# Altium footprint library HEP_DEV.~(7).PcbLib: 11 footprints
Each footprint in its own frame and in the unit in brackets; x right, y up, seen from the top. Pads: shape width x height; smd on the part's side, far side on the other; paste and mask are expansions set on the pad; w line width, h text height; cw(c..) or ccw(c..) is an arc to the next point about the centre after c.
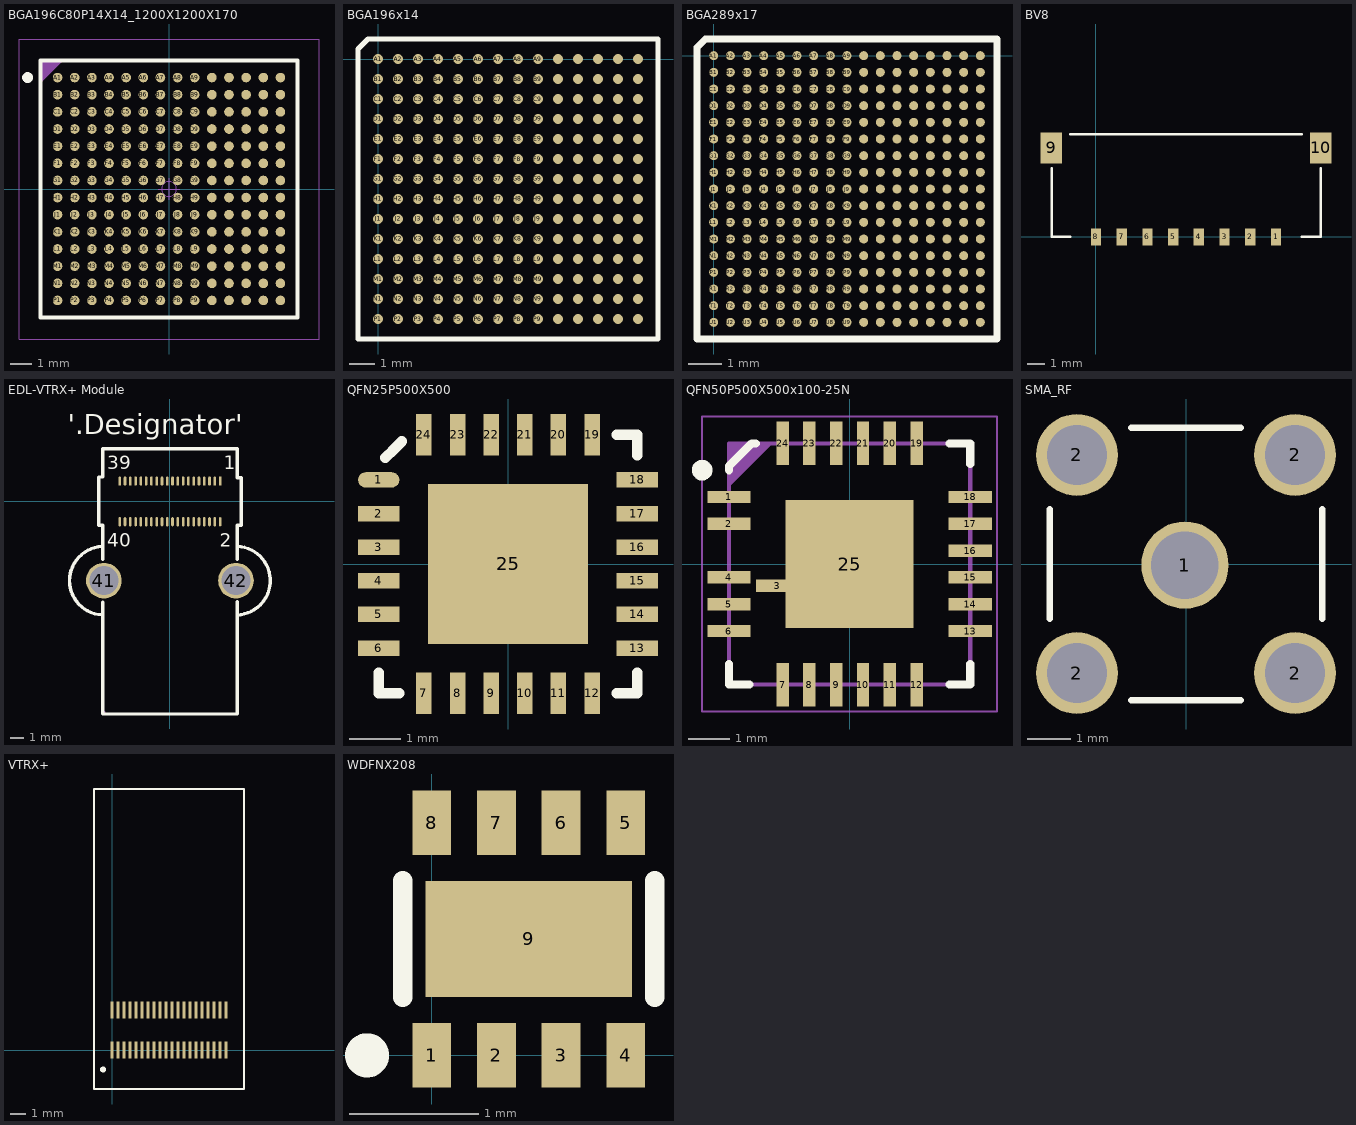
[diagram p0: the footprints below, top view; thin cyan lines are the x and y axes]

## BGA196C80P14X14_1200X1200X170 [mm] "BGA, 0.80mm Pitch, Square; 196 Pin, 14 Columns X 14 Rows, 12.00mm X 12.00mm X 1.70mm H"
height 1.7
pads (196):
  round 0.45 smd: A1(-5.2,5.2) A2(-4.4,5.2) A3(-3.6,5.2) A4(-2.8,5.2) A5(-2,5.2) A6(-1.2,5.2) A7(-0.4,5.2) A8(0.4,5.2) A9(1.2,5.2) A10(2,5.2) A11(2.8,5.2) A12(3.6,5.2) A13(4.4,5.2) A14(5.2,5.2) B1(-5.2,4.4) B2(-4.4,4.4) B3(-3.6,4.4) B4(-2.8,4.4) B5(-2,4.4) B6(-1.2,4.4) B7(-0.4,4.4) B8(0.4,4.4) B9(1.2,4.4) B10(2,4.4) B11(2.8,4.4) B12(3.6,4.4) B13(4.4,4.4) B14(5.2,4.4) C1(-5.2,3.6) C2(-4.4,3.6) C3(-3.6,3.6) C4(-2.8,3.6) C5(-2,3.6) C6(-1.2,3.6) C7(-0.4,3.6) C8(0.4,3.6) C9(1.2,3.6) C10(2,3.6) C11(2.8,3.6) C12(3.6,3.6) C13(4.4,3.6) C14(5.2,3.6) D1(-5.2,2.8) D2(-4.4,2.8) D3(-3.6,2.8) D4(-2.8,2.8) D5(-2,2.8) D6(-1.2,2.8) D7(-0.4,2.8) D8(0.4,2.8) D9(1.2,2.8) D10(2,2.8) D11(2.8,2.8) D12(3.6,2.8) D13(4.4,2.8) D14(5.2,2.8) E1(-5.2,2) E2(-4.4,2) E3(-3.6,2) E4(-2.8,2) E5(-2,2) E6(-1.2,2) E7(-0.4,2) E8(0.4,2) E9(1.2,2) E10(2,2) E11(2.8,2) E12(3.6,2) E13(4.4,2) E14(5.2,2) F1(-5.2,1.2) F2(-4.4,1.2) F3(-3.6,1.2) F4(-2.8,1.2) F5(-2,1.2) F6(-1.2,1.2) F7(-0.4,1.2) F8(0.4,1.2) F9(1.2,1.2) F10(2,1.2) F11(2.8,1.2) F12(3.6,1.2) F13(4.4,1.2) F14(5.2,1.2) G1(-5.2,0.4) G2(-4.4,0.4) G3(-3.6,0.4) G4(-2.8,0.4) G5(-2,0.4) G6(-1.2,0.4) G7(-0.4,0.4) G8(0.4,0.4) G9(1.2,0.4) G10(2,0.4) G11(2.8,0.4) G12(3.6,0.4) G13(4.4,0.4) G14(5.2,0.4) H1(-5.2,-0.4) H2(-4.4,-0.4) H3(-3.6,-0.4) H4(-2.8,-0.4) H5(-2,-0.4) H6(-1.2,-0.4) H7(-0.4,-0.4) H8(0.4,-0.4) H9(1.2,-0.4) H10(2,-0.4) H11(2.8,-0.4) H12(3.6,-0.4) H13(4.4,-0.4) H14(5.2,-0.4) J1(-5.2,-1.2) J2(-4.4,-1.2) J3(-3.6,-1.2) J4(-2.8,-1.2) J5(-2,-1.2) J6(-1.2,-1.2) J7(-0.4,-1.2) J8(0.4,-1.2) J9(1.2,-1.2) J10(2,-1.2) J11(2.8,-1.2) J12(3.6,-1.2) J13(4.4,-1.2) J14(5.2,-1.2) K1(-5.2,-2) K2(-4.4,-2) K3(-3.6,-2) K4(-2.8,-2) K5(-2,-2) K6(-1.2,-2) K7(-0.4,-2) K8(0.4,-2) K9(1.2,-2) K10(2,-2) K11(2.8,-2) K12(3.6,-2) K13(4.4,-2) K14(5.2,-2) L1(-5.2,-2.8) L2(-4.4,-2.8) L3(-3.6,-2.8) L4(-2.8,-2.8) L5(-2,-2.8) L6(-1.2,-2.8) L7(-0.4,-2.8) L8(0.4,-2.8) L9(1.2,-2.8) L10(2,-2.8) L11(2.8,-2.8) L12(3.6,-2.8) L13(4.4,-2.8) L14(5.2,-2.8) M1(-5.2,-3.6) M2(-4.4,-3.6) M3(-3.6,-3.6) M4(-2.8,-3.6) M5(-2,-3.6) M6(-1.2,-3.6) M7(-0.4,-3.6) M8(0.4,-3.6) M9(1.2,-3.6) M10(2,-3.6) M11(2.8,-3.6) M12(3.6,-3.6) M13(4.4,-3.6) M14(5.2,-3.6) N1(-5.2,-4.4) N2(-4.4,-4.4) N3(-3.6,-4.4) N4(-2.8,-4.4) N5(-2,-4.4) N6(-1.2,-4.4) N7(-0.4,-4.4) N8(0.4,-4.4) N9(1.2,-4.4) N10(2,-4.4) N11(2.8,-4.4) N12(3.6,-4.4) N13(4.4,-4.4) N14(5.2,-4.4) P1(-5.2,-5.2) P2(-4.4,-5.2) P3(-3.6,-5.2) P4(-2.8,-5.2) P5(-2,-5.2) P6(-1.2,-5.2) P7(-0.4,-5.2) P8(0.4,-5.2) P9(1.2,-5.2) P10(2,-5.2) P11(2.8,-5.2) P12(3.6,-5.2) P13(4.4,-5.2) P14(5.2,-5.2)
Top Overlay:
  circle w0.25: c-6.6,5.2 r0.125
  lines w0.2: -6,-6 -6,6 6,6 6,-6 -6,-6
Mechanical 14:
  lines w0.1: -6,5 -5,6 ; -6,5.1 -5.1,6 ; -6,5.2 -5.2,6 ; -6,5.3 -5.3,6 ; -6,5.4 -5.4,6 ; -6,5.5 -5.5,6 ; -6,5.6 -5.6,6 ; -6,5.7 -5.7,6 ; -6,5.8 -5.8,6 ; -6,5.9 -5.9,6 ; -6,-6 -6,6 6,6 6,-6 -6,-6
Mechanical 15:
  circle w0.05: c0,0 r0.35
  lines w0.05: -0.5,0 0.5,0 ; 0,-0.5 0,0.5 ; -7,-7 -7,7 7,7 7,-7 -7,-7
3D body "BGA196C80P14X14_1200X1200X170.stp": height 1.7, standoff 0, extent -6,-6 6,6

## BGA196x14 [mm]
pads (196):
  round 0.4 smd: A1(0,0) A2(0.8,0) A3(1.6,0) A4(2.4,0) A5(3.2,0) A6(4,0) A7(4.8,0) A8(5.6,0) A9(6.4,0) A10(7.2,0) A11(8,0) A12(8.8,0) A13(9.6,0) A14(10.4,0) B1(0,-0.8) B2(0.8,-0.8) B3(1.6,-0.8) B4(2.4,-0.8) B5(3.2,-0.8) B6(4,-0.8) B7(4.8,-0.8) B8(5.6,-0.8) B9(6.4,-0.8) B10(7.2,-0.8) B11(8,-0.8) B12(8.8,-0.8) B13(9.6,-0.8) B14(10.4,-0.8) C1(0,-1.6) C2(0.8,-1.6) C3(1.6,-1.6) C4(2.4,-1.6) C5(3.2,-1.6) C6(4,-1.6) C7(4.8,-1.6) C8(5.6,-1.6) C9(6.4,-1.6) C10(7.2,-1.6) C11(8,-1.6) C12(8.8,-1.6) C13(9.6,-1.6) C14(10.4,-1.6) D1(0,-2.4) D2(0.8,-2.4) D3(1.6,-2.4) D4(2.4,-2.4) D5(3.2,-2.4) D6(4,-2.4) D7(4.8,-2.4) D8(5.6,-2.4) D9(6.4,-2.4) D10(7.2,-2.4) D11(8,-2.4) D12(8.8,-2.4) D13(9.6,-2.4) D14(10.4,-2.4) E1(0,-3.2) E2(0.8,-3.2) E3(1.6,-3.2) E4(2.4,-3.2) E5(3.2,-3.2) E6(4,-3.2) E7(4.8,-3.2) E8(5.6,-3.2) E9(6.4,-3.2) E10(7.2,-3.2) E11(8,-3.2) E12(8.8,-3.2) E13(9.6,-3.2) E14(10.4,-3.2) F1(0,-4) F2(0.8,-4) F3(1.6,-4) F4(2.4,-4) F5(3.2,-4) F6(4,-4) F7(4.8,-4) F8(5.6,-4) F9(6.4,-4) F10(7.2,-4) F11(8,-4) F12(8.8,-4) F13(9.6,-4) F14(10.4,-4) G1(0,-4.8) G2(0.8,-4.8) G3(1.6,-4.8) G4(2.4,-4.8) G5(3.2,-4.8) G6(4,-4.8) G7(4.8,-4.8) G8(5.6,-4.8) G9(6.4,-4.8) G10(7.2,-4.8) G11(8,-4.8) G12(8.8,-4.8) G13(9.6,-4.8) G14(10.4,-4.8) H1(0,-5.6) H2(0.8,-5.6) H3(1.6,-5.6) H4(2.4,-5.6) H5(3.2,-5.6) H6(4,-5.6) H7(4.8,-5.6) H8(5.6,-5.6) H9(6.4,-5.6) H10(7.2,-5.6) H11(8,-5.6) H12(8.8,-5.6) H13(9.6,-5.6) H14(10.4,-5.6) J1(0,-6.4) J2(0.8,-6.4) J3(1.6,-6.4) J4(2.4,-6.4) J5(3.2,-6.4) J6(4,-6.4) J7(4.8,-6.4) J8(5.6,-6.4) J9(6.4,-6.4) J10(7.2,-6.4) J11(8,-6.4) J12(8.8,-6.4) J13(9.6,-6.4) J14(10.4,-6.4) K1(0,-7.2) K2(0.8,-7.2) K3(1.6,-7.2) K4(2.4,-7.2) K5(3.2,-7.2) K6(4,-7.2) K7(4.8,-7.2) K8(5.6,-7.2) K9(6.4,-7.2) K10(7.2,-7.2) K11(8,-7.2) K12(8.8,-7.2) K13(9.6,-7.2) K14(10.4,-7.2) L1(0,-8) L2(0.8,-8) L3(1.6,-8) L4(2.4,-8) L5(3.2,-8) L6(4,-8) L7(4.8,-8) L8(5.6,-8) L9(6.4,-8) L10(7.2,-8) L11(8,-8) L12(8.8,-8) L13(9.6,-8) L14(10.4,-8) M1(0,-8.8) M2(0.8,-8.8) M3(1.6,-8.8) M4(2.4,-8.8) M5(3.2,-8.8) M6(4,-8.8) M7(4.8,-8.8) M8(5.6,-8.8) M9(6.4,-8.8) M10(7.2,-8.8) M11(8,-8.8) M12(8.8,-8.8) M13(9.6,-8.8) M14(10.4,-8.8) N1(0,-9.6) N2(0.8,-9.6) N3(1.6,-9.6) N4(2.4,-9.6) N5(3.2,-9.6) N6(4,-9.6) N7(4.8,-9.6) N8(5.6,-9.6) N9(6.4,-9.6) N10(7.2,-9.6) N11(8,-9.6) N12(8.8,-9.6) N13(9.6,-9.6) N14(10.4,-9.6) P1(0,-10.4) P2(0.8,-10.4) P3(1.6,-10.4) P4(2.4,-10.4) P5(3.2,-10.4) P6(4,-10.4) P7(4.8,-10.4) P8(5.6,-10.4) P9(6.4,-10.4) P10(7.2,-10.4) P11(8,-10.4) P12(8.8,-10.4) P13(9.6,-10.4) P14(10.4,-10.4)
Top Overlay:
  lines w0.2: -0.8,-11.2 11.2,-11.2 11.2,0.8 -0.4,0.8 -0.8,0.4 -0.8,-11.2

## BGA289x17 [mm]
pads (289):
  round 0.27 smd: A1(0,0) A2(0.5,0) A3(1,0) A4(1.5,0) A5(2,0) A6(2.5,0) A7(3,0) A8(3.5,0) A9(4,0) A10(4.5,0) A11(5,0) A12(5.5,0) A13(6,0) A14(6.5,0) A15(7,0) A16(7.5,0) A17(8,0) B1(0,-0.5) B2(0.5,-0.5) B3(1,-0.5) B4(1.5,-0.5) B5(2,-0.5) B6(2.5,-0.5) B7(3,-0.5) B8(3.5,-0.5) B9(4,-0.5) B10(4.5,-0.5) B11(5,-0.5) B12(5.5,-0.5) B13(6,-0.5) B14(6.5,-0.5) B15(7,-0.5) B16(7.5,-0.5) B17(8,-0.5) C1(0,-1) C2(0.5,-1) C3(1,-1) C4(1.5,-1) C5(2,-1) C6(2.5,-1) C7(3,-1) C8(3.5,-1) C9(4,-1) C10(4.5,-1) C11(5,-1) C12(5.5,-1) C13(6,-1) C14(6.5,-1) C15(7,-1) C16(7.5,-1) C17(8,-1) D1(0,-1.5) D2(0.5,-1.5) D3(1,-1.5) D4(1.5,-1.5) D5(2,-1.5) D6(2.5,-1.5) D7(3,-1.5) D8(3.5,-1.5) D9(4,-1.5) D10(4.5,-1.5) D11(5,-1.5) D12(5.5,-1.5) D13(6,-1.5) D14(6.5,-1.5) D15(7,-1.5) D16(7.5,-1.5) D17(8,-1.5) E1(0,-2) E2(0.5,-2) E3(1,-2) E4(1.5,-2) E5(2,-2) E6(2.5,-2) E7(3,-2) E8(3.5,-2) E9(4,-2) E10(4.5,-2) E11(5,-2) E12(5.5,-2) E13(6,-2) E14(6.5,-2) E15(7,-2) E16(7.5,-2) E17(8,-2) F1(0,-2.5) F2(0.5,-2.5) F3(1,-2.5) F4(1.5,-2.5) F5(2,-2.5) F6(2.5,-2.5) F7(3,-2.5) F8(3.5,-2.5) F9(4,-2.5) F10(4.5,-2.5) F11(5,-2.5) F12(5.5,-2.5) F13(6,-2.5) F14(6.5,-2.5) F15(7,-2.5) F16(7.5,-2.5) F17(8,-2.5) G1(0,-3) G2(0.5,-3) G3(1,-3) G4(1.5,-3) G5(2,-3) G6(2.5,-3) G7(3,-3) G8(3.5,-3) G9(4,-3) G10(4.5,-3) G11(5,-3) G12(5.5,-3) G13(6,-3) G14(6.5,-3) G15(7,-3) G16(7.5,-3) G17(8,-3) H1(0,-3.5) H2(0.5,-3.5) H3(1,-3.5) H4(1.5,-3.5) H5(2,-3.5) H6(2.5,-3.5) H7(3,-3.5) H8(3.5,-3.5) H9(4,-3.5) H10(4.5,-3.5) H11(5,-3.5) H12(5.5,-3.5) H13(6,-3.5) H14(6.5,-3.5) H15(7,-3.5) H16(7.5,-3.5) H17(8,-3.5) J1(0,-4) J2(0.5,-4) J3(1,-4) J4(1.5,-4) J5(2,-4) J6(2.5,-4) J7(3,-4) J8(3.5,-4) J9(4,-4) J10(4.5,-4) J11(5,-4) J12(5.5,-4) J13(6,-4) J14(6.5,-4) J15(7,-4) J16(7.5,-4) J17(8,-4) K1(0,-4.5) K2(0.5,-4.5) K3(1,-4.5) K4(1.5,-4.5) K5(2,-4.5) K6(2.5,-4.5) K7(3,-4.5) K8(3.5,-4.5) K9(4,-4.5) K10(4.5,-4.5) K11(5,-4.5) K12(5.5,-4.5) K13(6,-4.5) K14(6.5,-4.5) K15(7,-4.5) K16(7.5,-4.5) K17(8,-4.5) L1(0,-5) L2(0.5,-5) L3(1,-5) L4(1.5,-5) L5(2,-5) L6(2.5,-5) L7(3,-5) L8(3.5,-5) L9(4,-5) L10(4.5,-5) L11(5,-5) L12(5.5,-5) L13(6,-5) L14(6.5,-5) L15(7,-5) L16(7.5,-5) L17(8,-5) M1(0,-5.5) M2(0.5,-5.5) M3(1,-5.5) M4(1.5,-5.5) M5(2,-5.5) M6(2.5,-5.5) M7(3,-5.5) M8(3.5,-5.5) M9(4,-5.5) M10(4.5,-5.5) M11(5,-5.5) M12(5.5,-5.5) M13(6,-5.5) M14(6.5,-5.5) M15(7,-5.5) M16(7.5,-5.5) M17(8,-5.5) N1(0,-6) N2(0.5,-6) N3(1,-6) N4(1.5,-6) N5(2,-6) N6(2.5,-6) N7(3,-6) N8(3.5,-6) N9(4,-6) N10(4.5,-6) N11(5,-6) N12(5.5,-6) N13(6,-6) N14(6.5,-6) N15(7,-6) N16(7.5,-6) N17(8,-6) P1(0,-6.5) P2(0.5,-6.5) P3(1,-6.5) P4(1.5,-6.5) P5(2,-6.5) P6(2.5,-6.5) P7(3,-6.5) P8(3.5,-6.5) P9(4,-6.5) P10(4.5,-6.5) P11(5,-6.5) P12(5.5,-6.5) P13(6,-6.5) P14(6.5,-6.5) P15(7,-6.5) P16(7.5,-6.5) P17(8,-6.5) R1(0,-7) R2(0.5,-7) R3(1,-7) R4(1.5,-7) R5(2,-7) R6(2.5,-7) R7(3,-7) R8(3.5,-7) R9(4,-7) R10(4.5,-7) R11(5,-7) R12(5.5,-7) R13(6,-7) R14(6.5,-7) R15(7,-7) R16(7.5,-7) R17(8,-7) T1(0,-7.5) T2(0.5,-7.5) T3(1,-7.5) T4(1.5,-7.5) T5(2,-7.5) T6(2.5,-7.5) T7(3,-7.5) T8(3.5,-7.5) T9(4,-7.5) T10(4.5,-7.5) T11(5,-7.5) T12(5.5,-7.5) T13(6,-7.5) T14(6.5,-7.5) T15(7,-7.5) T16(7.5,-7.5) T17(8,-7.5) U1(0,-8) U2(0.5,-8) U3(1,-8) U4(1.5,-8) U5(2,-8) U6(2.5,-8) U7(3,-8) U8(3.5,-8) U9(4,-8) U10(4.5,-8) U11(5,-8) U12(5.5,-8) U13(6,-8) U14(6.5,-8) U15(7,-8) U16(7.5,-8) U17(8,-8)
Top Overlay:
  lines w0.2: -0.5,-8.5 8.5,-8.5 8.5,0.5 -0.25,0.5 -0.5,0.25 -0.5,-8.5

## BV8 [mm]
pads (10):
  rect 0.6x1 smd: 1(10.5,0) 2(9,0) 3(7.5,0) 4(6,0) 5(4.5,0) 6(3,0) 7(1.5,0) 8(0,0)
  rect 1.25x1.8 smd: 9(-2.6,5.19) 10(13.1,5.19)
Top Overlay:
  lines w0.15: -2.575,4 -2.575,0 -1.5,0 ; -1.5,6 12,6 ; 12,0 13.1,0 13.1,4

## EDL-VTRX+ Module [mm]
height 3.3
pads (42):
  rect 0.2x0.7 smd: 1(3.8,1.54)
  oval 0.2x0.7 smd: 2(3.8,-1.54) 3(3.4,1.54) 4(3.4,-1.54) 5(3,1.54) 6(3,-1.54) 7(2.6,1.54) 8(2.6,-1.54) 9(2.2,1.54) 10(2.2,-1.54) 11(1.8,1.54) 12(1.8,-1.54) 13(1.4,1.54) 14(1.4,-1.54) 15(1,1.54) 16(1,-1.54) 17(0.6,1.54) 18(0.6,-1.54) 19(0.2,1.54) 20(0.2,-1.54) 21(-0.2,1.54) 22(-0.2,-1.54) 23(-0.6,1.54) 24(-0.6,-1.54) 25(-1,1.54) 26(-1,-1.54) 27(-1.4,1.54) 28(-1.4,-1.54) 29(-1.8,1.54) 30(-1.8,-1.54) 31(-2.2,1.54) 32(-2.2,-1.54) 33(-2.6,1.54) 34(-2.6,-1.54) 35(-3,1.54) 36(-3,-1.54) 37(-3.4,1.54) 38(-3.4,-1.54) 39(-3.8,1.54) 40(-3.8,-1.54)
  round 2.7 hole 2.2: 41(-5,-6) 42(5,-6)
Top Overlay:
  lines w0.254: -5.162,-3.405 ccw(c-5,-6) -5.158,-8.595 ; -5.1,-7.614 -5.1,-16.1 5.1,-16.1 5.1,-7.607 ; -5.1,-4.384 -5.1,-1.8 -5.4,-1.8 -5.4,1.845 ; 5.096,-8.598 ccw(c5,-6) 5.11,-3.402 ; 5.1,-4.388 5.1,-1.8 5.4,-1.8 5.4,1.8 ; 5.1,1.8 5.39,1.8 ; 5.1,1.835 5.1,4 -5.1,4 -5.1,1.845 ; -5.4,1.845 -5.1,1.845 ; -5.4,1.845 -5.1,1.845 ; -5.4,1.845 -5.1,1.845
  text "2" at 3.791,-3.428 h1.02
  text "40" at -4.744,-3.447 h1.02
  text "39" at -4.732,2.437 h1.02
  text "1" at 4.086,2.455 h1.02
  text "'.Designator'" at -7.738,5.098 h1.52
Bottom Overlay:
  circle w0.254: c5,-6 r2.6
  circle w0.254: c-5,-6 r2.6
Mechanical 1:
  lines w0.254: -5,-15.982 -4.991,-15.991
3D body "DF40C-40DP.stp": height 2.55, standoff 1.41, extent -4.771,-1.501 4.749,1.469
3D body: height 3.3, standoff 2.5, extent -5,-16 5,4
3D body "DF40C(2.0)-40DS.stp": height 1.91, standoff -0.04, extent -5.3,-1.69 5.3,1.69

## QFN25P500X500 [mm]
pads (25):
  oval 0.8x0.3 smd: 1(-2.5,1.625)
  rect 0.8x0.3 smd: 2(-2.5,0.975) 3(-2.5,0.325) 4(-2.5,-0.325) 5(-2.5,-0.975) 6(-2.5,-1.625) 13(2.5,-1.625) 14(2.5,-0.975) 15(2.5,-0.325) 16(2.5,0.325) 17(2.5,0.975) 18(2.5,1.625)
  rect 0.3x0.8 smd: 7(-1.625,-2.5) 8(-0.975,-2.5) 9(-0.325,-2.5) 10(0.325,-2.5) 11(0.975,-2.5) 12(1.625,-2.5) 19(1.625,2.5) 20(0.975,2.5) 21(0.325,2.5) 22(-0.325,2.5) 23(-0.975,2.5) 24(-1.625,2.5)
  rect 3.1x3.1 smd: 25(0,0)
Top Overlay:
  lines w0.203: -2.5,-2.5 -2.5,-2.1 ; -2.475,-2.5 -2.1,-2.5 ; -2.374,2.05 -2.212,2.212 ; -2.25,2.175 -2.05,2.375 ; 2.1,-2.5 2.5,-2.5 2.5,-2.1 ; 2.1,2.5 2.5,2.5 2.5,2.1
3D body: height 0.8, standoff 0, extent -2.487,-2.5 2.488,2.5

## QFN50P500X500x100-25N [mm] "QFN, 0.625mm Pitch, Square; 25 pin, 5.00mm L X 5.00mm W X 1.00mm H body (w/thermal tab 3.1 X 3.1mm),  IPC Medium Density"
height 0.8
pads (25):
  rect 1.05x0.3 smd: 1(-2.925,1.625) 2(-2.925,0.975) 3(-1.75,-0.525) 4(-2.925,-0.325) 5(-2.925,-0.975) 6(-2.925,-1.625) 13(2.925,-1.625) 14(2.925,-0.975) 15(2.925,-0.325) 16(2.925,0.325) 17(2.925,0.975) 18(2.925,1.625)
  rect 0.3x1.05 smd: 7(-1.625,-2.925) 8(-0.975,-2.925) 9(-0.325,-2.925) 10(0.325,-2.925) 11(0.975,-2.925) 12(1.625,-2.925) 19(1.625,2.925) 20(0.975,2.925) 21(0.325,2.925) 22(-0.325,2.925) 23(-0.975,2.925) 24(-1.625,2.925)
  rect 3.1x3.1 smd: 25(0,0)
Top Overlay:
  circle w0.25: c-3.575,2.275 r0.125
  lines w0.2: -2.925,-2.425 -2.925,-2.925 -2.425,-2.925 ; -2.925,2.275 -2.925,2.375 -2.375,2.925 -2.275,2.925 ; 2.425,-2.925 2.925,-2.925 2.925,-2.425 ; 2.425,2.925 2.925,2.925 2.925,2.425
Mechanical 14:
  lines w0.1: -2.925,1.925 -1.925,2.925 ; -2.925,2.025 -2.025,2.925 ; -2.925,2.125 -2.125,2.925 ; -2.925,2.225 -2.225,2.925 ; -2.925,2.325 -2.325,2.925 ; -2.925,2.425 -2.425,2.925 ; -2.925,2.525 -2.525,2.925 ; -2.925,2.625 -2.625,2.925 ; -2.925,2.725 -2.725,2.925 ; -2.925,2.825 -2.825,2.925 ; -2.925,-2.925 -2.925,2.925 2.925,2.925 2.925,-2.925 -2.925,-2.925
Mechanical 15:
  circle w0.05: c-0.325,0.325 r0.35
  lines w0.05: -0.825,0.325 0.175,0.325 ; -0.325,-0.175 -0.325,0.825 ; -3.575,-3.575 -3.575,3.575 3.575,3.575 3.575,-3.575 -3.575,-3.575
3D body: height 0.8, standoff 0, extent -2.925,-2.925 2.925,2.925

## SMA_RF [mil]
pads (5):
  round 80 hole 62: 1(-0.98,-0.98)
  round 75 hole 55: 2(-100,-100) 2(-100,100) 2(100,-100) 2(100,100)
Top Overlay:
  lines w5.91: -125,-50 -125,50 ; -50,-125 50,-125 ; -50,125 50,125 ; 125,-50 125,50

## VL+ concept [mm]
3D body: height 0.25, standoff 0, extent 40.64,-12.573 40.64,-12.573
3D body: height 2.5, standoff 0, extent -5,-10 5,10
3D body: height 0.25, standoff 0, extent -6.096,-9.906 -6.096,-9.906

## VTRX+ [mm]
pads (40):
  rect 0.2x1.12 smd: 1(0,0) 2(0,2.66) 3(0.4,0) 4(0.4,2.66) 5(0.8,0) 6(0.8,2.66) 7(1.2,0) 8(1.2,2.66) 9(1.6,0) 10(1.6,2.66) 11(2,0) 12(2,2.66) 13(2.4,0) 14(2.4,2.66) 15(2.8,0) 16(2.8,2.66) 17(3.2,0) 18(3.2,2.66) 19(3.6,0) 20(3.6,2.66) 21(4,0) 22(4,2.66) 23(4.4,0) 24(4.4,2.66) 25(4.8,0) 26(4.8,2.66) 27(5.2,0) 28(5.2,2.66) 29(5.6,0) 30(5.6,2.66) 31(6,0) 32(6,2.66) 33(6.4,0) 34(6.4,2.66) 35(6.8,0) 36(6.8,2.66) 37(7.2,0) 38(7.2,2.66) 39(7.6,0) 40(7.6,2.66)
Top Overlay:
  circle w0.2: c-0.6,-1.3 r0.1
  lines w0.15: -1.2,-2.6 -1.2,17.4 8.8,17.4 8.8,-2.6 -1.2,-2.6

## WDFNX208 [mm]
height 0.8
pads (9):
  rect 0.3x0.5 smd: 1(0,0) 2(0.5,0) 3(1,0) 4(1.5,0) 5(1.5,1.8) 6(1,1.8) 7(0.5,1.8) 8(0,1.8)
  rect 1.6x0.9 smd: 9(0.75,0.9)
Top Overlay:
  circle w0.2: c-0.5,0 r0.071
  lines w0.15: -0.225,0.45 -0.225,1.35 ; 1.725,0.45 1.725,1.35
